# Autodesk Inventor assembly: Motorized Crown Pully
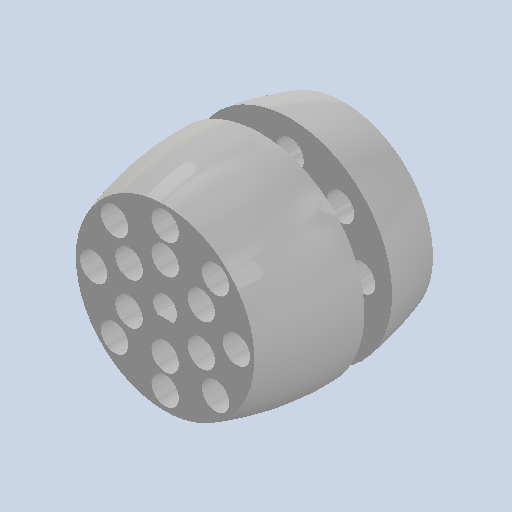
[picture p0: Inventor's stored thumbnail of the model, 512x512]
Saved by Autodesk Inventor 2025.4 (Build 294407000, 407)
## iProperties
Created: 2026-09
Part Number: Motorized Crown Pully
Document SubType Name: Assembly
Designer: AdminForWorker
Title: Motorized Crown Pully v10
Author: AdminForWorker
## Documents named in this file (5)
- c:\worker\convert-fusion-r05-cosv3\tmp\job-1\190\temp\files\1008992e-9ff1-4025-99f3-347864c0b9f8\3e4aa59c-bbaa-4019-b543-00849e1e86a2.iam
- c:\worker\convert-fusion-r05-cosv3\tmp\job-1\190\temp\files\1008992e-9ff1-4025-99f3-347864c0b9f8\Bearing 4_12 ID_OD v1.ipt
- c:\worker\convert-fusion-r05-cosv3\tmp\job-1\190\temp\files\1008992e-9ff1-4025-99f3-347864c0b9f8\Roller Dowel 20mm v1.ipt
- c:\worker\convert-fusion-r05-cosv3\tmp\job-1\190\temp\files\1008992e-9ff1-4025-99f3-347864c0b9f8\bottom.ipt
- c:\worker\convert-fusion-r05-cosv3\tmp\job-1\190\temp\files\1008992e-9ff1-4025-99f3-347864c0b9f8\top.ipt
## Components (4 placed, 4 different names)
1. Bearing 4/12 ID/OD v1:1
2. Roller Dowel 20mm v1:1
3. bottom:1
4. top:1
